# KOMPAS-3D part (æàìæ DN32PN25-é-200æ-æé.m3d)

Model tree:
1. Объединить компоненты:1  (labels: СЕНС DN32PN25-В-200С)
2. Эскиз:1
3. Операция выдавливания:1
     Расстояние 1 = 14
4. Фаска:1
     Угол = 45; Длина 1 = 2; Длина 2 = 2

Referenced files in D:\Савин\!СЕНСОР\3D для заказчика\!Новый перечень\СЕНС\4. СЕНС-В-200С\DN32\: СЕНС DN32PN25-В-200С.a3d
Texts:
  СЕНС DN32PN25-В-200С-СВ
  ООО НПП Сенсор
  СЕНС DN32PN25-В-200С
